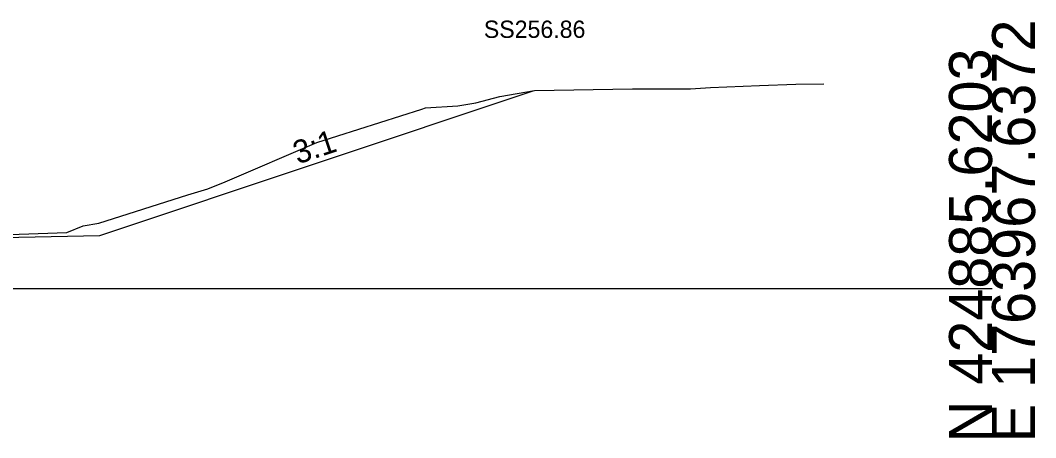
# Model space of a CAD drawing. Extents: x -26 to 3203, y -11010 to 4024.
# Drawn here: x 3136.8 to 3202.8, y -4509.7 to -4482.6 of the extents above; entities that cross this region are included whole.
import ezdxf

# ---------------------------------------------------------------- set-up
doc = ezdxf.new("R2010")
doc.units = 0
for name, color, linetype in [('Exist Cross Section Cell', 7, 'Continuous'), ('Exist XS Ground Line', 7, 'Continuous'), ('Prop CMT Slope Grass', 7, 'Continuous'), ('Prop XS Side Slope Text', 7, 'Continuous'), ('Prop XS SS Elevation Text', 7, 'Continuous'), ('Scratch_Level_0', 7, 'Continuous')]:
    doc.layers.add(name, color=color, linetype=linetype)

msp = doc.modelspace()

# ---------------------------------------------------------------- linework, layer by layer
at = {"layer": 'Exist Cross Section Cell'}
msp.add_line((3100, -4500), (3200, -4500), dxfattribs=at)
at = {"layer": 'Exist XS Ground Line'}
msp.add_lwpolyline([(3135.432, -4496.506), (3139.779, -4496.349), (3140.841, -4495.916), (3141.868, -4495.74), (3147.664, -4493.916), (3148.956, -4493.508), (3150.082, -4493.065), (3156.044, -4490.506), (3162.887, -4488.337), (3163.132, -4488.263), (3165.236, -4488.133), (3166.4, -4487.92), (3167.955, -4487.521), (3170.219, -4487.13), (3176.608, -4487.008), (3180.372, -4487.016), (3181.683, -4486.937), (3184.864, -4486.795), (3187.224, -4486.724), (3189.044, -4486.683)], dxfattribs=at)
msp.add_lwpolyline([(3135.432, -4496.506), (3139.779, -4496.349), (3140.841, -4495.916), (3141.868, -4495.74), (3147.664, -4493.916), (3148.956, -4493.508), (3150.082, -4493.065), (3156.044, -4490.506), (3162.887, -4488.337), (3163.132, -4488.263), (3165.236, -4488.133), (3166.4, -4487.92), (3167.955, -4487.521), (3170.219, -4487.13), (3176.608, -4487.008), (3180.372, -4487.016), (3181.683, -4486.937), (3184.864, -4486.795), (3187.224, -4486.724), (3189.044, -4486.683)], dxfattribs=at)
msp.add_lwpolyline([(3135.432, -4496.506), (3139.779, -4496.349), (3140.841, -4495.916), (3141.868, -4495.74), (3147.664, -4493.916), (3148.956, -4493.508), (3150.082, -4493.065), (3156.044, -4490.506), (3162.887, -4488.337), (3163.132, -4488.263), (3165.236, -4488.133), (3166.4, -4487.92), (3167.955, -4487.521), (3170.219, -4487.13), (3176.608, -4487.008), (3180.372, -4487.016), (3181.683, -4486.937), (3184.864, -4486.795), (3187.224, -4486.724), (3189.044, -4486.683)], dxfattribs=at)
msp.add_lwpolyline([(3135.432, -4496.506), (3139.779, -4496.349), (3140.841, -4495.916), (3141.868, -4495.74), (3147.664, -4493.916), (3148.956, -4493.508), (3150.082, -4493.065), (3156.044, -4490.506), (3162.887, -4488.337), (3163.132, -4488.263), (3165.236, -4488.133), (3166.4, -4487.92), (3167.955, -4487.521), (3170.219, -4487.13), (3176.608, -4487.008), (3180.372, -4487.016), (3181.683, -4486.937), (3184.864, -4486.795), (3187.224, -4486.724), (3189.044, -4486.683)], dxfattribs=at)
msp.add_lwpolyline([(3135.432, -4496.506), (3139.779, -4496.349), (3140.841, -4495.916), (3141.868, -4495.74), (3147.664, -4493.916), (3148.956, -4493.508), (3150.082, -4493.065), (3156.044, -4490.506), (3162.887, -4488.337), (3163.132, -4488.263), (3165.236, -4488.133), (3166.4, -4487.92), (3167.955, -4487.521), (3170.219, -4487.13), (3176.608, -4487.008), (3180.372, -4487.016), (3181.683, -4486.937), (3184.864, -4486.795), (3187.224, -4486.724), (3189.044, -4486.683)], dxfattribs=at)
at = {"layer": 'Prop CMT Slope Grass'}
msp.add_lwpolyline([(3132.427, -4496.737), (3141.927, -4496.547), (3170.134, -4487.145)], dxfattribs=at)

# ---------------------------------------------------------------- texts
at = {"layer": 'Exist Cross Section Cell'}
for s, p in [('E 1763967.6372', (3202.8, -4510)), ('N 424885.6203', (3200, -4510))]:
    msp.add_text(s, height=2.8, rotation=90, dxfattribs=at).set_placement(p)
at = {"layer": 'Prop XS Side Slope Text'}
msp.add_text('3:1', height=1.5, rotation=18.43493, dxfattribs=at).set_placement((3154.808, -4491.937))
at = {"layer": 'Prop XS SS Elevation Text'}
msp.add_text('SS256.86', height=1.125, dxfattribs=at).set_placement((3166.923, -4483.707))
at = {"layer": 'Scratch_Level_0'}
for s, p in [('Exterior Boundary', (3169.975, -4487.155)), ('RT_Slope_Cut', (3170.03, -4487.155)), ('RT_CSLP_Pnt', (3141.829, -4496.557))]:
    msp.add_text(s, height=0.02, dxfattribs=at).set_placement(p)

doc.saveas('drawing.dxf')
